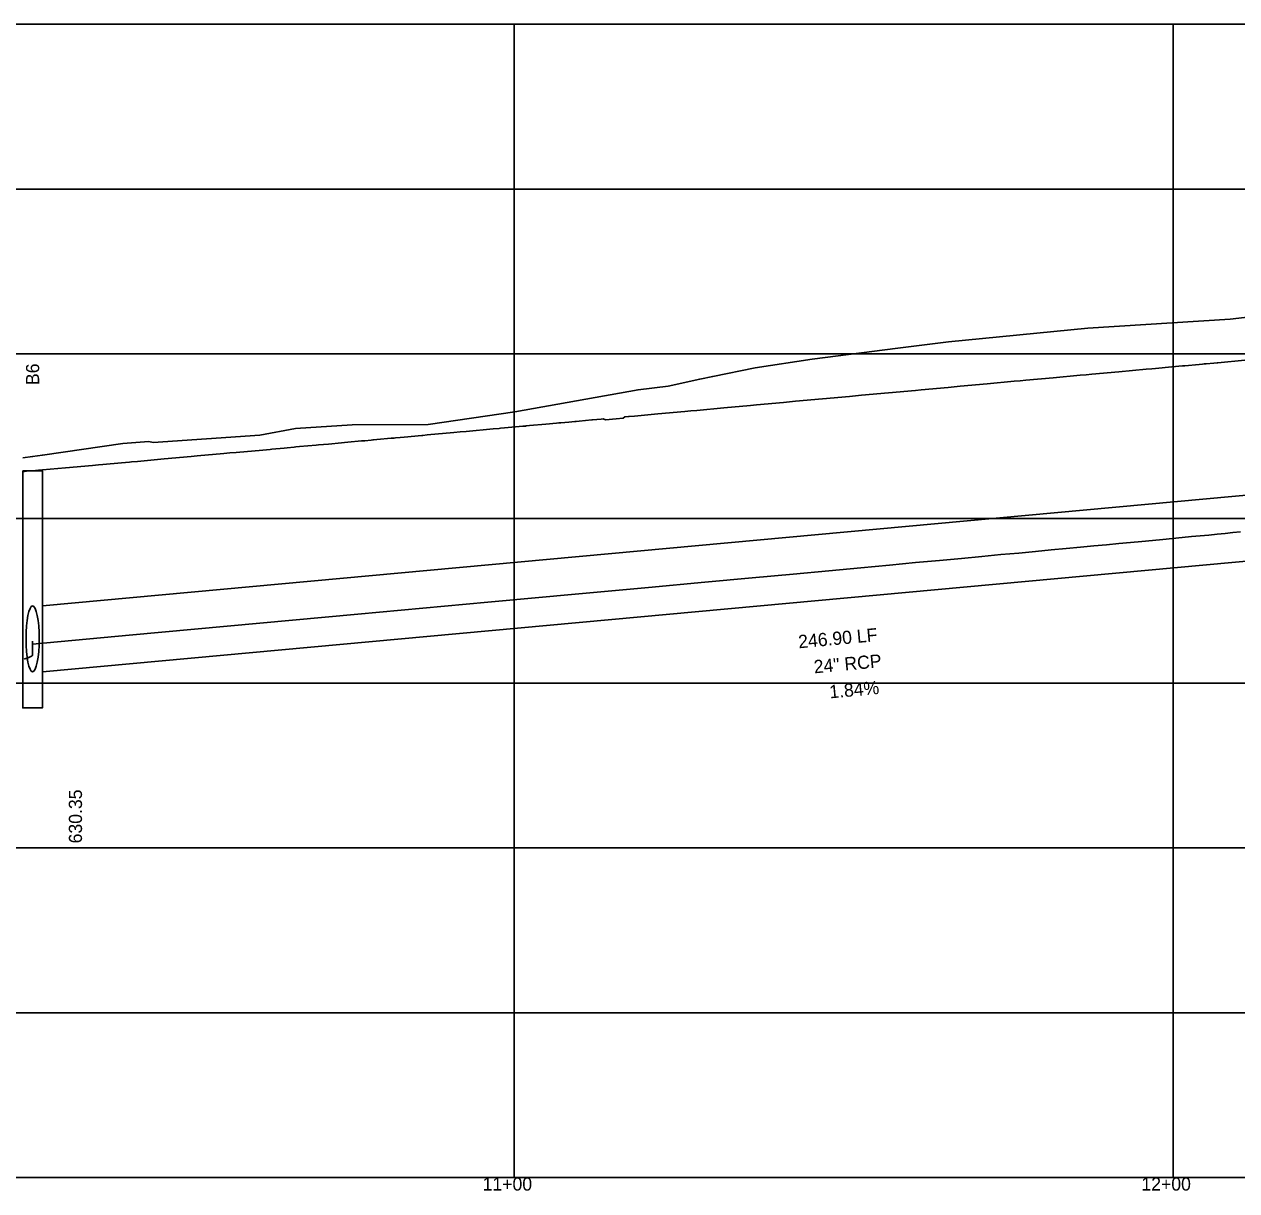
# Model space of a CAD drawing. Extents: x 2254979 to 2278074, y 13790855 to 13792793.
# Drawn here: x 2260986.3 to 2261170.4, y 13792139.4 to 13792316.4 of the extents above; entities that cross this region are included whole.
import ezdxf

# ---------------------------------------------------------------- set-up
doc = ezdxf.new("R2010")
doc.units = 0
for name, color, linetype in [('blank4', 7, 'Continuous'), ('D_DRN_PROF_HGL', 7, 'Continuous'), ('D_PROF_1', 7, 'Continuous'), ('D_PROF_NOTES_1', 7, 'Continuous'), ('Default', 7, 'Continuous'), ('Drain_PipeInside', 7, 'Continuous'), ('E_Terrain', 7, 'Continuous'), ('Inlet', 7, 'Continuous'), ('z - Construction', 7, 'Continuous')]:
    doc.layers.add(name, color=color, linetype=linetype)

msp = doc.modelspace()

# ---------------------------------------------------------------- linework, layer by layer
at = {"layer": 'blank4'}
msp.add_lwpolyline([(2259960.69, 13792141.44), (2259960.69, 13792316.44), (2261351.48, 13792316.44), (2261351.48, 13792141.44)], close=True, dxfattribs=at)
at = {"layer": 'D_DRN_PROF_HGL'}
msp.add_line((2260987.58, 13792222.83), (2260987.58, 13792222.36), dxfattribs=at)
for points in [[(2260987.58, 13792222.36), (2261002.23, 13792223.71), (2261036.94, 13792226.91), (2261056.7, 13792228.73), (2261070.49, 13792230), (2261081.06, 13792230.98), (2261089.63, 13792231.77), (2261096.82, 13792232.43), (2261103.01, 13792233.01), (2261108.44, 13792233.51), (2261113.28, 13792233.96), (2261117.64, 13792234.37), (2261121.59, 13792234.74), (2261125.22, 13792235.08), (2261128.57, 13792235.39), (2261131.67, 13792235.68), (2261134.56, 13792235.95), (2261137.27, 13792236.2), (2261139.81, 13792236.44), (2261142.21, 13792236.67), (2261144.47, 13792236.88), (2261146.62, 13792237.08), (2261148.66, 13792237.27), (2261150.61, 13792237.46), (2261152.46, 13792237.63), (2261154.24, 13792237.8), (2261155.93, 13792237.96), (2261157.56, 13792238.12), (2261159.13, 13792238.27), (2261160.63, 13792238.41), (2261162.08, 13792238.55), (2261163.48, 13792238.68), (2261164.82, 13792238.81), (2261166.13, 13792238.93), (2261167.39, 13792239.06), (2261168.6, 13792239.17), (2261169.78, 13792239.29), (2261170.93, 13792239.4)], [(2260986.3, 13792220.11), (2260986.33, 13792220.12), (2260986.37, 13792220.13), (2260986.4, 13792220.14), (2260986.43, 13792220.15), (2260986.46, 13792220.16), (2260986.49, 13792220.17), (2260986.52, 13792220.18), (2260986.55, 13792220.19), (2260986.58, 13792220.2), (2260986.6, 13792220.21), (2260986.63, 13792220.21), (2260986.66, 13792220.22), (2260986.69, 13792220.23), (2260986.71, 13792220.24), (2260986.74, 13792220.25), (2260986.76, 13792220.26), (2260986.79, 13792220.27), (2260986.81, 13792220.28), (2260986.84, 13792220.29), (2260986.86, 13792220.29), (2260986.88, 13792220.3), (2260986.91, 13792220.31), (2260986.93, 13792220.32), (2260986.95, 13792220.33), (2260986.97, 13792220.34), (2260986.99, 13792220.34), (2260987.02, 13792220.35), (2260987.04, 13792220.36), (2260987.06, 13792220.37), (2260987.07, 13792220.38), (2260987.09, 13792220.38), (2260987.11, 13792220.39), (2260987.13, 13792220.4), (2260987.15, 13792220.41), (2260987.17, 13792220.41), (2260987.18, 13792220.42), (2260987.2, 13792220.43), (2260987.22, 13792220.44), (2260987.23, 13792220.44), (2260987.25, 13792220.45), (2260987.26, 13792220.46), (2260987.28, 13792220.47), (2260987.29, 13792220.47), (2260987.31, 13792220.48), (2260987.32, 13792220.49), (2260987.33, 13792220.49), (2260987.34, 13792220.5), (2260987.36, 13792220.51), (2260987.37, 13792220.51), (2260987.38, 13792220.52), (2260987.39, 13792220.53), (2260987.4, 13792220.53), (2260987.41, 13792220.54), (2260987.42, 13792220.55), (2260987.43, 13792220.55), (2260987.44, 13792220.56), (2260987.45, 13792220.57), (2260987.46, 13792220.57), (2260987.47, 13792220.58), (2260987.48, 13792220.59), (2260987.49, 13792220.59), (2260987.49, 13792220.6), (2260987.5, 13792220.6), (2260987.51, 13792220.61), (2260987.51, 13792220.62), (2260987.52, 13792220.62), (2260987.53, 13792220.63), (2260987.53, 13792220.63), (2260987.54, 13792220.64), (2260987.54, 13792220.65), (2260987.55, 13792220.65), (2260987.55, 13792220.66), (2260987.55, 13792220.66), (2260987.56, 13792220.67), (2260987.56, 13792220.67), (2260987.56, 13792220.68), (2260987.57, 13792220.68), (2260987.57, 13792220.69), (2260987.57, 13792220.69), (2260987.57, 13792220.7), (2260987.57, 13792220.7), (2260987.58, 13792220.71), (2260987.58, 13792220.72), (2260987.58, 13792220.72), (2260987.58, 13792220.73), (2260987.58, 13792222.83)]]:
    msp.add_lwpolyline(points, dxfattribs=at)
at = {"layer": 'D_PROF_1'}
msp.add_lwpolyline([(2260986.08, 13792248.54), (2260986.67, 13792248.6), (2260987.58, 13792248.68), (2260987.58, 13792248.68), (2260988.48, 13792248.76), (2260989.08, 13792248.82), (2260989.08, 13792248.82), (2260992.58, 13792249.13), (2260996.66, 13792249.5), (2260997.58, 13792249.58), (2260998.22, 13792249.64), (2261001.09, 13792249.9), (2261002.3, 13792250), (2261002.57, 13792250.03), (2261003.49, 13792250.11), (2261007.56, 13792250.48), (2261011.63, 13792250.85), (2261012.55, 13792250.93), (2261016.61, 13792251.3), (2261017.54, 13792251.38), (2261018.47, 13792251.47), (2261022.53, 13792251.83), (2261023.62, 13792251.93), (2261023.87, 13792251.96), (2261025.79, 13792252.13), (2261026.23, 13792252.17), (2261027.28, 13792252.27), (2261027.52, 13792252.29), (2261028.1, 13792252.34), (2261030.6, 13792252.57), (2261030.96, 13792252.6), (2261032.51, 13792252.74), (2261034.49, 13792252.92), (2261034.94, 13792252.96), (2261035.42, 13792253.01), (2261037.5, 13792253.2), (2261037.92, 13792253.24), (2261038.01, 13792253.24), (2261038.99, 13792253.33), (2261039.21, 13792253.35), (2261039.33, 13792253.36), (2261039.83, 13792253.41), (2261041.99, 13792253.61), (2261042.48, 13792253.65), (2261042.65, 13792253.67), (2261043.38, 13792253.73), (2261043.99, 13792253.79), (2261046.65, 13792254.04), (2261046.81, 13792254.05), (2261047.47, 13792254.11), (2261051.53, 13792254.48), (2261052.48, 13792254.57), (2261053.41, 13792254.65), (2261057.48, 13792255.02), (2261058.38, 13792255.11), (2261058.59, 13792255.13), (2261059.23, 13792255.18), (2261061.99, 13792255.44), (2261062.39, 13792255.47), (2261062.48, 13792255.48), (2261063.03, 13792255.53), (2261065.47, 13792255.75), (2261067.1, 13792255.9), (2261067.48, 13792255.94), (2261067.76, 13792255.96), (2261069, 13792256.08), (2261069.88, 13792256.16), (2261070.08, 13792256.18), (2261070.52, 13792256.22), (2261072.48, 13792256.4), (2261072.49, 13792256.4), (2261072.56, 13792256.4), (2261073.88, 13792256.52), (2261074.18, 13792256.55), (2261074.54, 13792256.43), (2261076.14, 13792256.58), (2261077.23, 13792256.68), (2261077.48, 13792256.85), (2261078.02, 13792256.9), (2261078.14, 13792256.91), (2261078.94, 13792256.99), (2261082.48, 13792257.31), (2261086.56, 13792257.68), (2261087.48, 13792257.77), (2261088.39, 13792257.85), (2261092.48, 13792258.22), (2261096.56, 13792258.6), (2261097.48, 13792258.68), (2261101.56, 13792259.05), (2261102.48, 13792259.14), (2261103.39, 13792259.22), (2261107.48, 13792259.6), (2261111.57, 13792259.97), (2261112.48, 13792260.05), (2261113.38, 13792260.13), (2261117.48, 13792260.51), (2261121.58, 13792260.88), (2261122.48, 13792260.97), (2261126.58, 13792261.34), (2261127.48, 13792261.42), (2261128.37, 13792261.51), (2261132.48, 13792261.88), (2261136.58, 13792262.26), (2261137.48, 13792262.34), (2261138.37, 13792262.42), (2261142.48, 13792262.79), (2261146.59, 13792263.17), (2261147.48, 13792263.25), (2261148.36, 13792263.33), (2261152.48, 13792263.71), (2261156.6, 13792264.09), (2261157.48, 13792264.17), (2261158.01, 13792264.22), (2261160.53, 13792264.45), (2261162.13, 13792264.59), (2261162.48, 13792264.62), (2261164.68, 13792264.82), (2261165.15, 13792264.87), (2261165.43, 13792264.89), (2261165.49, 13792264.9), (2261165.73, 13792264.92), (2261166.9, 13792265.03), (2261167.38, 13792265.07), (2261167.48, 13792265.08), (2261171.61, 13792265.46)], dxfattribs=at)
at = {"layer": 'Default'}
for p, q in [((2261060.69, 13792141.44), (2261060.69, 13792316.44)), ((2261160.69, 13792141.44), (2261160.69, 13792316.44))]:
    msp.add_line(p, q, dxfattribs=at)
at = {"layer": 'Drain_PipeInside'}
for p, q in [((2260989.08, 13792228.18), (2261235.98, 13792250.87)), ((2260989.08, 13792218.18), (2261235.98, 13792240.87))]:
    msp.add_line(p, q, dxfattribs=at)
msp.add_ellipse((2260987.58, 13792223.18), major_axis=(0, 5), ratio=0.2, dxfattribs=at)
msp.add_ellipse((2260987.58, 13792223.18), major_axis=(0, 5), ratio=0.2, dxfattribs=at)
at = {"layer": 'E_Terrain'}
msp.add_lwpolyline([(2260986.08, 13792250.62), (2260987.58, 13792250.84), (2260987.58, 13792250.84), (2260989.08, 13792251.07), (2260989.08, 13792251.07), (2261001.3, 13792252.83), (2261005.22, 13792253.13), (2261005.86, 13792252.97), (2261022.05, 13792254.06), (2261027.47, 13792255.08), (2261036.07, 13792255.65), (2261047.62, 13792255.72), (2261060.76, 13792257.6), (2261079.48, 13792260.97), (2261084.05, 13792261.5), (2261088.85, 13792262.59), (2261090.83, 13792263.01), (2261097.28, 13792264.32), (2261105.92, 13792265.64), (2261118.91, 13792267.28), (2261126.6, 13792268.26), (2261147.74, 13792270.31), (2261169.35, 13792271.67), (2261175.42, 13792272.4)], dxfattribs=at)
at = {"layer": 'Inlet'}
msp.add_lwpolyline([(2260986.08, 13792248.68), (2260989.08, 13792248.68), (2260989.08, 13792212.69), (2260986.08, 13792212.69)], close=True, dxfattribs=at)
at = {"layer": 'z - Construction'}
for p, q in [((2259960.69, 13792291.44), (2261351.48, 13792291.44)), ((2259960.69, 13792266.44), (2261351.48, 13792266.44)), ((2259960.69, 13792241.44), (2261351.48, 13792241.44)), ((2259960.69, 13792216.44), (2261351.48, 13792216.44)), ((2259960.69, 13792191.44), (2261351.48, 13792191.44)), ((2259960.69, 13792166.44), (2261351.48, 13792166.44))]:
    msp.add_line(p, q, dxfattribs=at)

# ---------------------------------------------------------------- texts
at = {"layer": 'D_PROF_NOTES_1'}
for s, rotation, p in [('B6', 90, (2260988.58, 13792261.69)), ('246.90 LF', 5.2507, (2261103.89, 13792221.73)), ('24" RCP', 5.2507, (2261106.25, 13792217.93)), ('1.84%', 5.2507, (2261108.61, 13792214.13)), ('630.35', 90, (2260995.08, 13792192.13))]:
    msp.add_text(s, height=2, rotation=rotation, dxfattribs=at).set_placement(p)
at = {"layer": 'Default'}
for s, p in [('11+00', (2261055.89, 13792139.44)), ('12+00', (2261155.89, 13792139.44))]:
    msp.add_text(s, height=2, dxfattribs=at).set_placement(p)

doc.saveas('drawing.dxf')
